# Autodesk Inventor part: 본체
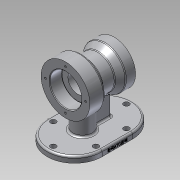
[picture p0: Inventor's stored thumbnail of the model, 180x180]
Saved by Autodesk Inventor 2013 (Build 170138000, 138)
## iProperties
Created: 2020-01
Part Number: 본체
Material: 알루미늄 6061
Document SubType Name: Modeling
Designer: Administrator
Density: 2.71 g/cm^3
Mass: 924.16 g
Surface Area: 656.156 cm^2
Volume: 341.018 cm^3
Author: Administrator
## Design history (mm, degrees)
sketch "스케치1"
  geometry: L1 (-40, 0)-(40, 0); L2 (-40, 0)-(-40, 26); L3 (-40, 40)-(-16, 40); L4 (-16, 40)-(-7.247, 27.5); L5 (-7.247, 27.5)-(13.289, 27.5); L6 (13.289, 27.5)-(24, 35); L7 (24, 35)-(40, 35); L8 (40, 35)-(40, 20); L9 (-20, 26)-(-20, 16); L10 (-20, 16)-(23, 16); L11 (23, 16)-(23, 20); L12 (23, 20)-(40, 20); L13 (-20, 26)-(-40, 26); L14 (-40, 26)-(-40, 40); L15 (40, 20)-(40, 0); 1 further point
  constraints: 30 end point, 10 parallel, 7 perpendicular, 2 midpoint, 1 horizontal
  dimensions: "d0" = 80 distance of L1.start L1.end; "d2" = 80 diameter of L3 L1; "d5" = 24 distance of L3.start L3.end; "d8" = 35 deg angle of L6 L5; "d9" = 16 distance of L6.end L7.end; "d10" = 70 diameter of L7 L1; "d11" = 55 diameter of L5 L1; "d12" = 52 diameter of L13 L1; "d13" = 32 diameter of L10 L1; "d14" = 40 diameter of L12 L1; "d15" = 20 distance of L9.start L2.end; "d16" = 17 distance of L11.end L8.end
revolve "회전1" sketch "스케치1" stored, may be unused: angle "d17" = 90 deg
sketch "스케치2"
  geometry: L1 (-70, -70)-(70, -70); L2 (70, -70)-(70, -80); L3 (70, -80)-(-70, -80); L4 (-70, -80)-(-70, -70); L5 (-40, -40)-(-40, 40) reference; 1 further point
  constraints: 8 end point, 2 parallel, 1 horizontal, 1 perpendicular
  dimensions: "d18" = 10 distance of L1.end L2.end; "d20" = 140 distance of L2.end L3.end; "d21" = 30 distance between parallel lines of L4 L5; "d22" = 80 distance from line of point (0, 0) L3
extrude "돌출1" join sketch "스케치2" stored distance "d23" = 90; taper "d24" = 0 deg
sketch "스케치3"
  geometry: L1 (0, 90)-(0, 0) reference; C1 r 16 at (58, 45); 2 further points
  constraints: 1 centre point, 1 horizontal alignment, 1 midpoint
  dimensions: "d25" = 32 diameter of C1; "d27" = 58 distance from line of C1.centre L1
extrude "돌출2" join sketch "스케치3" stored distance "d28" = 0; taper "d29" = 0 deg
sketch "스케치4"
  geometry: L1 (30, -70)-(30, -35); L2 (24, -35)-(40, -35) reference; L3 (-70, -70)-(70, -70) reference; L4 (40, -35)-(40, 35) reference; 1 further point
  constraints: 2 end point, 2 point on line, 1 vertical
  dimensions: "d30" = 10 distance between parallel lines of L4 L1
feature "리브1" sketch "스케치4" dims "d31" = 1, "d32" = 10, "d33" = 0, "d34" = 0, "d35" = 1, "d36" = 1
fillet "모깎기1" dims "d37" = 45
sketch "스케치5"
  geometry: C1 r 26 at (0, 0) reference; 1 further point
  constraints: 1 vertical alignment
  dimensions: "d38" = 33 distance of C1.centre point (0, 33)
hole "구멍1" sketch "스케치5" at (0, 33) diameter "d39" = 3.242; stored, may be unused: countersink angle "d43" = 90 deg, drill point angle "d45" = 118 deg; dims "d40" = 9, "d41" = 4, "d42" = 2, "d44" = 11
sketch "스케치6"
  geometry: C1 r 20 at (0, 0) reference; 1 further point
  constraints: 1 vertical alignment
  dimensions: "d49" = 27.5 distance of C1.centre point (0, 27.5)
hole "구멍2" sketch "스케치6" at (0, 27.5) diameter "d50" = 3.242; stored, may be unused: countersink angle "d54" = 90 deg, drill point angle "d56" = 118 deg; dims "d51" = 9, "d52" = 4, "d53" = 2, "d55" = 11
sketch "스케치7"
  geometry: L1 (50, 0)-(0, 0) reference; L2 (0, 90)-(50, 90) reference; L3 (50, 10)-(0, 10); L4 (0, 80)-(50, 80); A1 r 45 centre (0, 45) between (0, 90) and (0, 0) reference; A2 r 45 centre (50, 45) between (50, 0) and (50, 90) reference; A3 r 35 centre (50, 45) between (50, 10) and (50, 80); A4 r 35 centre (0, 45) between (0, 80) and (0, 10); 7 further points
  constraints: 6 point on circle, 4 coincident, 4 end point, 2 centre point, 3 other
  dimensions: "d60" = 35 radius of A3
hole "구멍3" sketch "스케치7" at (0, 80), (50, 80), (50, 10), (0, 10), (-35, 45), (85, 45) diameter "d62" = 9; stored, may be unused: countersink angle "d66" = 90 deg, drill point angle "d68" = 0 deg; dims "d63" = 9, "d64" = 4, "d65" = 2, "d67" = 11
sketch "스케치8"
  geometry: L1 (-70, -70)-(-70, -80) reference; L2 (70, -80)-(25, -80) reference; 2 further points
  constraints: 1 other
  dimensions: "d69" = 70 distance from line of point (0, -76) L1; "d70" = 4 distance from line of L2 point (0, -76)
feature "엠보싱1" sketch "스케치8" dims "d18" = 10, "d20" = 140, "d21" = 30, "d22" = 80, "d71" = 0.5, "d72" = 0
chamfer "모따기1" distance "d73" = 1; stored, may be unused: second distance "d74" = 2, angle "d75" = 45 deg
fillet "모깎기2" dims "d76" = 0.3
fillet "모깎기3" dims "d77" = 3
fillet "모깎기4" dims "d78" = 3
fillet "모깎기5" dims "d79" = 3
fillet "모깎기6" dims "d80" = 3
fillet "모깎기7" dims "d81" = 3
node "솔리드1"
pattern_circular "원형 패턴1" dims angle "d47" = 360 deg
pattern_circular "원형 패턴2" dims angle "d58" = 360 deg
